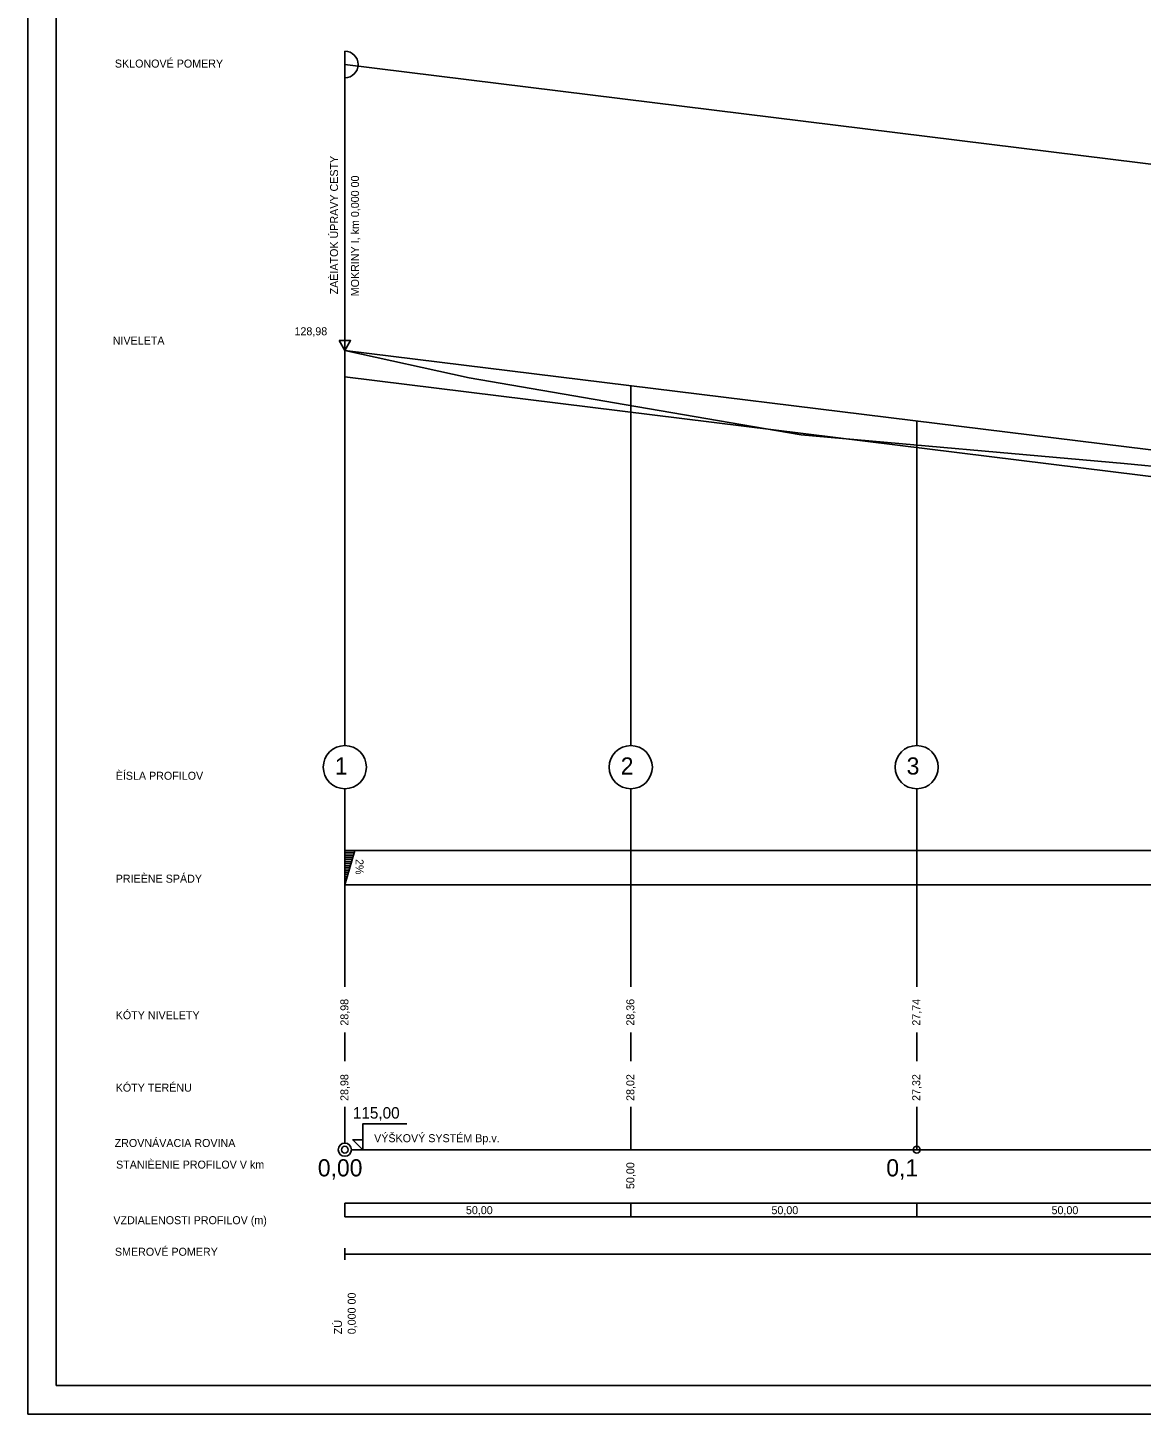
# Model space of a CAD drawing. Extents: x -499093 to -498458, y -1280289 to -1279879.
# Drawn here: x -499093.4 to -498898.7, y -1280289.4 to -1280046.9 of the extents above; entities that cross this region are included whole.
import ezdxf

# ---------------------------------------------------------------- set-up
doc = ezdxf.new("R2010")
doc.units = 0
for name, color, linetype in [('Vrstva 1', 7, 'Continuous'), ('Vrstva 11', 7, 'Continuous'), ('Vrstva 12', 7, 'Continuous'), ('Vrstva 13', 7, 'Continuous'), ('Vrstva 4', 7, 'Continuous'), ('Vrstva 8', 7, 'Continuous')]:
    doc.layers.add(name, color=color, linetype=linetype)

# ---------------------------------------------------------------- blocks, each defined once
blk = doc.blocks.new('SC97995')
at = {"layer": 'Vrstva 1'}
blk.add_line((0, 0), (0, 0), dxfattribs=at)

msp = doc.modelspace()

# ---------------------------------------------------------------- linework, layer by layer
at = {"layer": 'Vrstva 1'}
for p, q in [((-499093.41, -1279879.38), (-499093.41, -1280289.38)), ((-499088.41, -1279884.38), (-499088.41, -1280284.38)), ((-499088.41, -1280284.38), (-498468.41, -1280284.38)), ((-499093.41, -1280289.38), (-498463.41, -1280289.38))]:
    msp.add_line(p, q, dxfattribs=at)
at = {"layer": 'Vrstva 11'}
for p, q in [((-499037.95, -1280103.31), (-498707.77, -1280144.11)), ((-499036.2, -1280190.82), (-499037.95, -1280190.82)), ((-499036.31, -1280191.2), (-499037.95, -1280191.2)), ((-499036.42, -1280191.57), (-499037.95, -1280191.57)), ((-499036.53, -1280191.95), (-499037.95, -1280191.95)), ((-499036.64, -1280192.32), (-499037.95, -1280192.32)), ((-499036.75, -1280192.7), (-499037.95, -1280192.7)), ((-499036.86, -1280193.07), (-499037.95, -1280193.07)), ((-499036.96, -1280193.45), (-499037.95, -1280193.45)), ((-499037.07, -1280193.82), (-499037.95, -1280193.82)), ((-499037.18, -1280194.2), (-499037.95, -1280194.2)), ((-499037.29, -1280194.57), (-499037.95, -1280194.57)), ((-499037.4, -1280194.95), (-499037.95, -1280194.95)), ((-499037.51, -1280195.32), (-499037.95, -1280195.32)), ((-499037.62, -1280195.7), (-499037.95, -1280195.7)), ((-499037.73, -1280196.07), (-499037.95, -1280196.07)), ((-499037.84, -1280196.45), (-499037.95, -1280196.45)), ((-499036.78, -1280243.11), (-498707.77, -1280243.11)), ((-498987.95, -1280252.46), (-498987.95, -1280254.86)), ((-498937.95, -1280252.46), (-498937.95, -1280254.86))]:
    msp.add_line(p, q, dxfattribs=at)
msp.add_lwpolyline([(-499037.95, -1280190.81), (-499037.95, -1280196.81), (-499036.2, -1280190.81), (-499037.95, -1280190.81)], dxfattribs=at)
for centre in [(-499037.95, -1280176.21), (-498987.95, -1280176.21), (-498937.95, -1280176.21)]:
    msp.add_circle(centre, 3.77, dxfattribs=at)
at = {"layer": 'Vrstva 13'}
for p, q in [((-499037.95, -1280172.45), (-499037.95, -1280050.98)), ((-499037.95, -1280053.31), (-498707.77, -1280094.11)), ((-499037.95, -1280103.31), (-499016.2, -1280108.11)), ((-499016.2, -1280108.11), (-498987.05, -1280113.11)), ((-498987.95, -1280172.45), (-498987.95, -1280109.49)), ((-498987.05, -1280113.11), (-498958.18, -1280118.11)), ((-498937.95, -1280172.45), (-498937.95, -1280115.67)), ((-498958.18, -1280118.11), (-498901.65, -1280123.11)), ((-498901.65, -1280123.11), (-498848.05, -1280128.11)), ((-499037.95, -1280214.61), (-499037.95, -1280179.98)), ((-498987.95, -1280214.61), (-498987.95, -1280179.98)), ((-498937.95, -1280214.61), (-498937.95, -1280179.98)), ((-499037.95, -1280190.81), (-498707.77, -1280190.81)), ((-499037.95, -1280196.81), (-498707.77, -1280196.81)), ((-499037.95, -1280227.61), (-499037.95, -1280222.61)), ((-498987.95, -1280227.61), (-498987.95, -1280222.61)), ((-498937.95, -1280227.61), (-498937.95, -1280222.61)), ((-499037.95, -1280241.95), (-499037.95, -1280235.61)), ((-498987.95, -1280243.11), (-498987.95, -1280235.61)), ((-498937.95, -1280243.11), (-498937.95, -1280235.61)), ((-499036.78, -1280243.11), (-498938.54, -1280243.11))]:
    msp.add_line(p, q, dxfattribs=at)
for points in [[(-499038.93, -1280101.59), (-499037.95, -1280103.31), (-499036.96, -1280101.59), (-499038.93, -1280101.59)], [(-499034.81, -1280241.41), (-499036.58, -1280241.41), (-499034.81, -1280243.11), (-499034.81, -1280238.6), (-499027.12, -1280238.6)]]:
    msp.add_lwpolyline(points, dxfattribs=at)
for centre, radius in [((-499037.95, -1280243.11), 1.16), ((-499037.95, -1280243.11), 0.592), ((-498937.95, -1280243.11), 0.592)]:
    msp.add_circle(centre, radius, dxfattribs=at)
msp.add_arc((-499037.95, -1280053.31), 2.33, 270, 90, dxfattribs=at)
at = {"layer": 'Vrstva 8'}
for p, q in [((-499037.95, -1280107.94), (-498707.77, -1280148.74)), ((-499036.78, -1280243.11), (-498707.77, -1280243.11)), ((-499037.95, -1280252.46), (-498707.77, -1280252.46)), ((-499037.95, -1280252.46), (-499037.95, -1280254.86)), ((-499037.95, -1280254.86), (-498707.77, -1280254.86)), ((-499037.95, -1280262.36), (-499037.95, -1280260.36)), ((-499037.95, -1280261.36), (-498707.77, -1280261.36))]:
    msp.add_line(p, q, dxfattribs=at)

# ---------------------------------------------------------------- block references
at = {"layer": 'Vrstva 11'}
msp.add_blockref('SC97995', (-499037.95, -1280103.31), dxfattribs=at)

# ---------------------------------------------------------------- texts
at = {"layer": 'Vrstva 12'}
for s, rotation, p in [('ZAÈIATOK ÚPRAVY CESTY', 90, (-499039.14, -1280093.52)), ('MOKRINY I, km 0,000 00', 90, (-499035.48, -1280093.85)), ('2%', 270, (-499036.08, -1280192.28)), ('28,98', 90, (-499037.33, -1280221.42)), ('28,36', 90, (-498987.33, -1280221.42)), ('27,74', 90, (-498937.33, -1280221.42)), ('28,98', 90, (-499037.33, -1280234.58)), ('28,02', 90, (-498987.33, -1280234.58)), ('27,32', 90, (-498937.33, -1280234.58)), ('50,00', 90, (-498987.33, -1280249.99)), ('0,000 00', 90, (-499036.05, -1280275.39)), ('ZÚ', 90, (-499038.45, -1280275.39))]:
    msp.add_text(s, height=1.4, rotation=rotation, dxfattribs=at).set_placement(p)
for s, height, p in [('128,98', 1.4, (-499046.76, -1280100.67)), ('1', 3, (-499039.71, -1280177.5)), ('2', 3, (-498989.71, -1280177.5)), ('3', 3, (-498939.71, -1280177.5)), ('KÓTY TERÉNU', 1.4, (-499078.02, -1280232.96)), ('115,00', 2, (-499036.55, -1280237.67)), ('VÝŠKOVÝ SYSTÉM Bp.v.', 1.4, (-499032.83, -1280241.8)), ('0,00', 3, (-499042.68, -1280247.78)), ('0,1', 3, (-498943.27, -1280247.78)), ('50,00', 1.4, (-499016.78, -1280254.39)), ('50,00', 1.4, (-498963.35, -1280254.39)), ('50,00', 1.4, (-498914.37, -1280254.39))]:
    msp.add_text(s, height=height, dxfattribs=at).set_placement(p)
at = {"layer": 'Vrstva 4'}
for s, p in [('SKLONOVÉ POMERY', (-499078.17, -1280053.85)), ('NIVELETA', (-499078.54, -1280102.3)), ('ÈÍSLA PROFILOV', (-499078.02, -1280178.41)), ('PRIEÈNE SPÁDY', (-499078.02, -1280196.41)), ('KÓTY NIVELETY', (-499078.02, -1280220.29)), ('ZROVNÁVACIA ROVINA', (-499078.21, -1280242.64)), ('STANIÈENIE PROFILOV V km', (-499077.96, -1280246.42)), ('VZDIALENOSTI PROFILOV (m)', (-499078.43, -1280256.14)), ('SMEROVÉ POMERY', (-499078.16, -1280261.66))]:
    msp.add_text(s, height=1.4, dxfattribs=at).set_placement(p)

doc.saveas('drawing.dxf')
